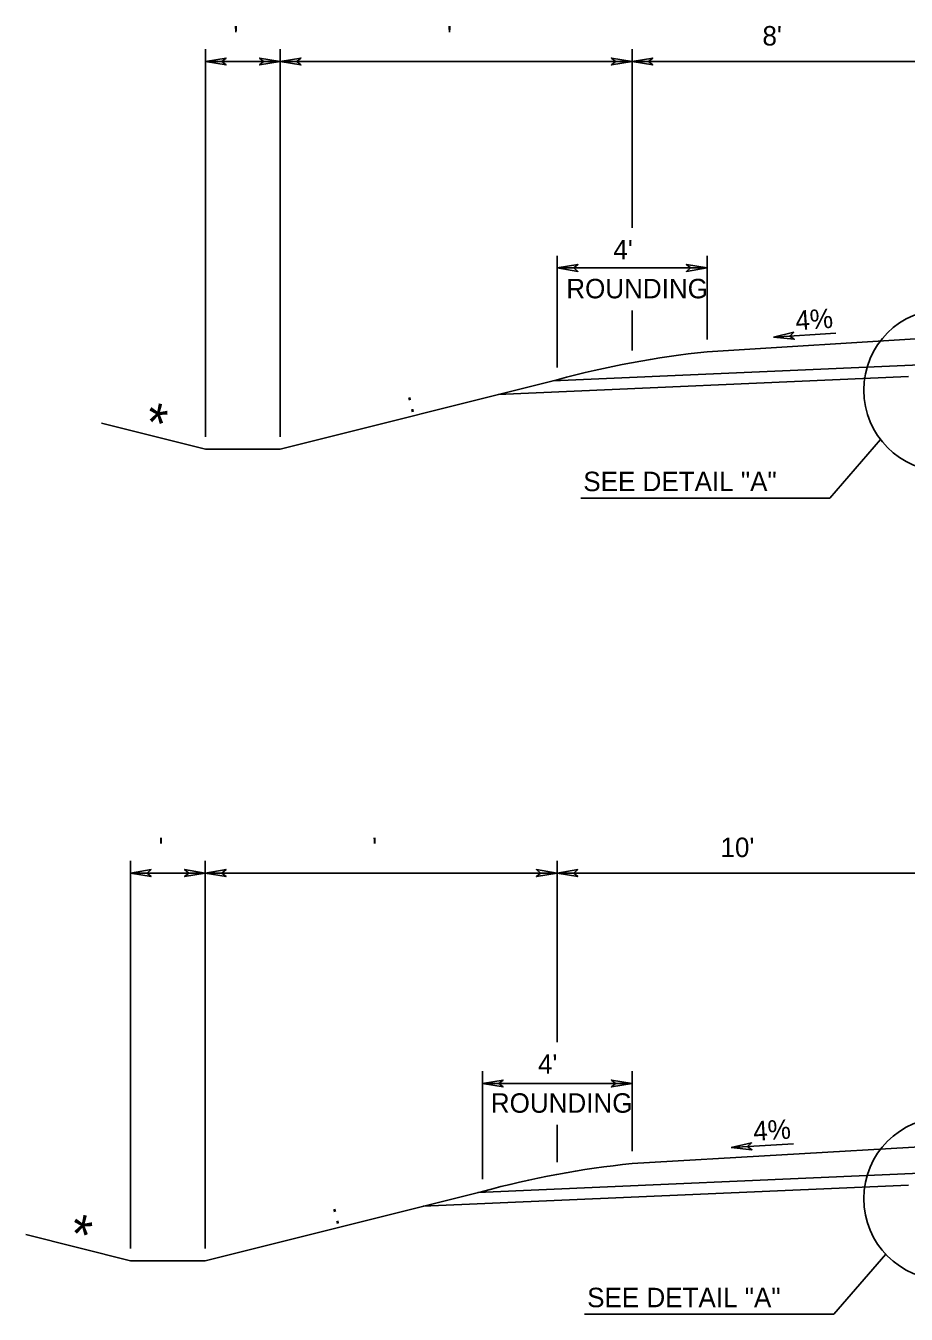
# Model space of a CAD drawing. Extents: x -540 to 1231, y -564 to 421.
# Drawn here: x -93.4 to -30, y 72.7 to 165.4 of the extents above; entities that cross this region are included whole.
import ezdxf

# ---------------------------------------------------------------- set-up
doc = ezdxf.new("R2010")
doc.units = 0
doc.layers.add('1', color=7, linetype='Continuous')
doc.layers.add('Des_ Drain_ Ftrs', color=7, linetype='Continuous')

msp = doc.modelspace()

# ---------------------------------------------------------------- linework, layer by layer
at = {"layer": '1'}
for p, q in [((-80.459, 135.794), (-80.459, 163.665)), ((-75.071, 135.794), (-75.071, 163.665)), ((-49.752, 150.814), (-49.752, 163.665)), ((-75.071, 162.785), (-80.459, 162.785)), ((-49.752, 162.785), (-75.071, 162.785)), ((-28.199, 162.785), (-49.752, 162.785)), ((-55.13, 140.779), (-55.13, 148.819)), ((-44.353, 142.788), (-44.353, 148.819)), ((-44.353, 147.939), (-55.13, 147.939)), ((-49.752, 142.009), (-49.752, 144.877)), ((-44.353, 141.908), (-28.204, 142.923)), ((-39.583, 142.97), (-35.094, 143.252)), ((-55.463, 139.816), (1.437, 142.3)), ((-59.388, 138.834), (-29.846, 140.125)), ((-55.13, 139.899), (-75.071, 134.914)), ((-87.937, 136.783), (-80.459, 134.914)), ((-35.512, 131.383), (-31.864, 135.597)), ((-75.071, 134.914), (-80.459, 134.914)), ((-53.444, 131.383), (-35.512, 131.383)), ((-85.848, 77.421), (-85.848, 105.298)), ((-80.46, 77.421), (-80.46, 105.298)), ((-55.143, 92.254), (-55.143, 105.298)), ((-80.46, 104.418), (-85.848, 104.418)), ((-55.143, 104.418), (-80.46, 104.418)), ((-28.201, 104.418), (-55.143, 104.418)), ((-60.521, 82.398), (-60.521, 90.161)), ((-49.744, 84.406), (-49.744, 90.161)), ((-49.744, 89.281), (-60.521, 89.281)), ((-55.143, 83.627), (-55.143, 86.304)), ((-49.744, 83.526), (-28.206, 84.778)), ((-42.625, 84.684), (-38.134, 84.934)), ((-60.848, 81.436), (1.434, 84.156)), ((-64.776, 80.456), (-29.848, 81.981)), ((-60.521, 81.518), (-80.46, 76.541)), ((-93.383, 78.425), (-85.848, 76.541)), ((-35.236, 72.689), (-31.496, 77.009)), ((-80.46, 76.541), (-85.848, 76.541)), ((-53.167, 72.689), (-35.236, 72.689))]:
    msp.add_line(p, q, dxfattribs=at)
for centre in [(-27.234, 139.145), (-27.236, 81.001)]:
    msp.add_circle(centre, 5.838, dxfattribs=at)
for centre in [(-37.471, 75.073), (-42.862, 16.692)]:
    msp.add_arc(centre, 67.188, 95.87953, 105.23809, dxfattribs=at)
at = {"layer": 'Des_ Drain_ Ftrs'}
for points in [[(-80.459, 162.785), (-78.971, 162.537), (-79.266, 162.785), (-78.971, 163.034)], [(-75.071, 162.785), (-76.559, 162.537), (-76.264, 162.785), (-76.559, 163.034)], [(-75.071, 162.785), (-73.583, 162.537), (-73.878, 162.785), (-73.583, 163.034)], [(-49.752, 162.785), (-51.24, 162.537), (-50.945, 162.785), (-51.24, 163.034)], [(-49.752, 162.785), (-48.264, 162.537), (-48.559, 162.785), (-48.264, 163.034)], [(-55.13, 147.939), (-53.641, 147.691), (-53.936, 147.939), (-53.641, 148.187)], [(-44.353, 147.939), (-45.842, 147.691), (-45.547, 147.939), (-45.842, 148.187)], [(-39.583, 142.97), (-38.082, 142.814), (-38.392, 143.044), (-38.113, 143.31)], [(-85.848, 104.418), (-84.36, 104.169), (-84.655, 104.418), (-84.36, 104.666)], [(-80.46, 104.418), (-81.948, 104.169), (-81.653, 104.418), (-81.948, 104.666)], [(-80.46, 104.418), (-78.971, 104.169), (-79.266, 104.418), (-78.971, 104.666)], [(-55.143, 104.418), (-56.631, 104.169), (-56.336, 104.418), (-56.631, 104.666)], [(-55.143, 104.418), (-53.655, 104.169), (-53.95, 104.418), (-53.655, 104.666)], [(-60.521, 89.281), (-59.032, 89.033), (-59.327, 89.281), (-59.032, 89.529)], [(-49.744, 89.281), (-51.232, 89.033), (-50.937, 89.281), (-51.232, 89.529)], [(-42.625, 84.684), (-41.126, 84.517), (-41.434, 84.749), (-41.153, 85.013)]]:
    msp.add_lwpolyline(points, close=True, dxfattribs=at)

# ---------------------------------------------------------------- texts
at = {"layer": '1'}
for s, p in [(" '", (-78.96, 163.937)), ("  '", (-64.107, 163.937)), ("8'", (-40.366, 163.937)), ("4'", (-51.094, 148.555)), ('ROUNDING', (-54.483, 145.755)), ('SEE DETAIL "A"', (-53.259, 131.886)), (" '", (-84.349, 105.569)), ("  '", (-69.497, 105.569)), ("10'", (-43.387, 105.569)), ("4'", (-56.523, 89.981)), ('ROUNDING', (-59.912, 87.181)), ('SEE DETAIL "A"', (-52.982, 73.193))]:
    msp.add_text(s, height=1.4, dxfattribs=at).set_placement(p)
for s, height, rotation, p in [('4%', 1.4, 3.87905, (-37.951, 143.456)), ('*', 2.8, 347.15207, (-85.024, 135.603)), (' : ', 1.4, 14.22821, (-66.28, 137.393)), ('4%', 1.4, 3.46407, (-40.99, 85.159)), ('*', 2.8, 347.15207, (-90.442, 77.238)), (' : ', 1.4, 14.22821, (-71.669, 79.017))]:
    msp.add_text(s, height=height, rotation=rotation, dxfattribs=at).set_placement(p)

doc.saveas('drawing.dxf')
